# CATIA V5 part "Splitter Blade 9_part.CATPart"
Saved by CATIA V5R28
Part number: Splitter Blade 9_part
Definition: design
Nomenclature: Splitter Blade 9_part
Source: Unknown
Bounding box of the stored display mesh (mm): x -6.333 to 2.096, y -7.963 to -3.498, z 4.237 to 7.742
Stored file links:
  D:\paraturbo-cad\STEP\Turbocompressor_for_Christophe\Splitter Blade 9_part.CATPart
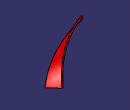
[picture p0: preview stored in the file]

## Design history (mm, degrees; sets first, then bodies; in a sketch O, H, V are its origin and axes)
Body1 "MANIFOLD_SOLID_BREP #78128" (main body)
  Solid1: solid without history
